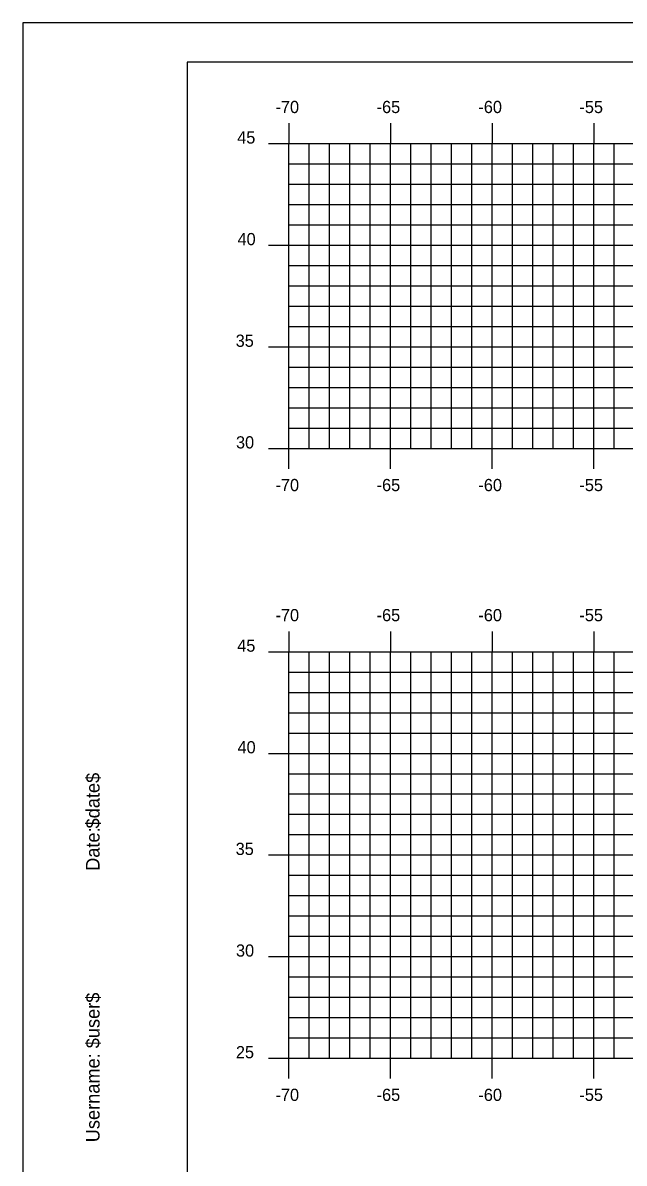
# Model space of a CAD drawing. Extents: x 1026799 to 1026969, y 394697 to 394807.
# Drawn here: x 1026799.3 to 1026828.8, y 394750.4 to 394806.5 of the extents above; entities that cross this region are included whole.
import ezdxf

# ---------------------------------------------------------------- set-up
doc = ezdxf.new("R2010")
doc.units = 0
for name, color, linetype in [('BORDER', 7, 'Continuous'), ('H_V ANNOTATION', 7, 'Continuous'), ('MAJOR', 7, 'Continuous'), ('MINOR', 7, 'Continuous'), ('PLOT BOUNDARY', 7, 'Continuous')]:
    doc.layers.add(name, color=color, linetype=linetype)

msp = doc.modelspace()

# ---------------------------------------------------------------- linework, layer by layer
at = {"layer": 'BORDER'}
for p, q in [((1026967.348, 394804.607), (1026807.348, 394804.607)), ((1026807.348, 394804.607), (1026807.348, 394699.607))]:
    msp.add_line(p, q, dxfattribs=at)
at = {"layer": 'MAJOR'}
for p, q in [((1026812.348, 394801.609), (1026812.348, 394800.607)), ((1026817.348, 394801.609), (1026817.348, 394800.607)), ((1026822.348, 394801.609), (1026822.348, 394800.607)), ((1026827.348, 394801.609), (1026827.348, 394800.607)), ((1026811.346, 394800.607), (1026812.348, 394800.607)), ((1026812.348, 394800.607), (1026952.348, 394800.607)), ((1026812.348, 394785.607), (1026812.348, 394800.607)), ((1026817.348, 394785.607), (1026817.348, 394800.607)), ((1026822.348, 394785.607), (1026822.348, 394800.607)), ((1026827.348, 394785.607), (1026827.348, 394800.607)), ((1026811.346, 394795.607), (1026812.348, 394795.607)), ((1026812.348, 394795.607), (1026952.348, 394795.607)), ((1026811.346, 394790.607), (1026812.348, 394790.607)), ((1026812.348, 394790.607), (1026952.348, 394790.607)), ((1026811.346, 394785.607), (1026812.348, 394785.607)), ((1026812.348, 394785.607), (1026952.348, 394785.607)), ((1026812.348, 394784.605), (1026812.348, 394785.607)), ((1026817.348, 394784.605), (1026817.348, 394785.607)), ((1026822.348, 394784.605), (1026822.348, 394785.607)), ((1026827.348, 394784.605), (1026827.348, 394785.607)), ((1026812.348, 394776.609), (1026812.348, 394775.607)), ((1026817.348, 394776.609), (1026817.348, 394775.607)), ((1026822.348, 394776.609), (1026822.348, 394775.607)), ((1026827.348, 394776.609), (1026827.348, 394775.607)), ((1026811.346, 394775.607), (1026812.348, 394775.607)), ((1026812.348, 394775.607), (1026952.348, 394775.607)), ((1026812.348, 394755.607), (1026812.348, 394775.607)), ((1026817.348, 394755.607), (1026817.348, 394775.607)), ((1026822.348, 394755.607), (1026822.348, 394775.607)), ((1026827.348, 394755.607), (1026827.348, 394775.607)), ((1026811.346, 394770.607), (1026812.348, 394770.607)), ((1026812.348, 394770.607), (1026952.348, 394770.607)), ((1026811.346, 394765.607), (1026812.348, 394765.607)), ((1026812.348, 394765.607), (1026952.348, 394765.607)), ((1026811.346, 394760.607), (1026812.348, 394760.607)), ((1026812.348, 394760.607), (1026952.348, 394760.607)), ((1026811.346, 394755.607), (1026812.348, 394755.607)), ((1026812.348, 394755.607), (1026952.348, 394755.607)), ((1026812.348, 394754.605), (1026812.348, 394755.607)), ((1026817.348, 394754.605), (1026817.348, 394755.607)), ((1026822.348, 394754.605), (1026822.348, 394755.607)), ((1026827.348, 394754.605), (1026827.348, 394755.607))]:
    msp.add_line(p, q, dxfattribs=at)
at = {"layer": 'MINOR'}
for p, q in [((1026813.348, 394785.607), (1026813.348, 394800.607)), ((1026814.348, 394785.607), (1026814.348, 394800.607)), ((1026815.348, 394785.607), (1026815.348, 394800.607)), ((1026816.348, 394785.607), (1026816.348, 394800.607)), ((1026818.348, 394785.607), (1026818.348, 394800.607)), ((1026819.348, 394785.607), (1026819.348, 394800.607)), ((1026820.348, 394785.607), (1026820.348, 394800.607)), ((1026821.348, 394785.607), (1026821.348, 394800.607)), ((1026823.348, 394785.607), (1026823.348, 394800.607)), ((1026824.348, 394785.607), (1026824.348, 394800.607)), ((1026825.348, 394785.607), (1026825.348, 394800.607)), ((1026826.348, 394785.607), (1026826.348, 394800.607)), ((1026828.348, 394785.607), (1026828.348, 394800.607)), ((1026812.348, 394799.607), (1026952.348, 394799.607)), ((1026812.348, 394799.607), (1026813.35, 394799.607)), ((1026812.348, 394798.607), (1026952.348, 394798.607)), ((1026812.348, 394798.607), (1026813.35, 394798.607)), ((1026812.348, 394797.607), (1026952.348, 394797.607)), ((1026812.348, 394797.607), (1026813.35, 394797.607)), ((1026812.348, 394796.607), (1026952.348, 394796.607)), ((1026812.348, 394796.607), (1026813.35, 394796.607)), ((1026812.348, 394794.607), (1026952.348, 394794.607)), ((1026812.348, 394794.607), (1026813.35, 394794.607)), ((1026812.348, 394793.607), (1026952.348, 394793.607)), ((1026812.348, 394793.607), (1026813.35, 394793.607)), ((1026812.348, 394792.607), (1026952.348, 394792.607)), ((1026812.348, 394792.607), (1026813.35, 394792.607)), ((1026812.348, 394791.607), (1026952.348, 394791.607)), ((1026812.348, 394791.607), (1026813.35, 394791.607)), ((1026812.348, 394789.607), (1026952.348, 394789.607)), ((1026812.348, 394789.607), (1026813.35, 394789.607)), ((1026812.348, 394788.607), (1026952.348, 394788.607)), ((1026812.348, 394788.607), (1026813.35, 394788.607)), ((1026812.348, 394787.607), (1026952.348, 394787.607)), ((1026812.348, 394787.607), (1026813.35, 394787.607)), ((1026812.348, 394786.607), (1026952.348, 394786.607)), ((1026812.348, 394786.607), (1026813.35, 394786.607)), ((1026813.348, 394755.607), (1026813.348, 394775.607)), ((1026814.348, 394755.607), (1026814.348, 394775.607)), ((1026815.348, 394755.607), (1026815.348, 394775.607)), ((1026816.348, 394755.607), (1026816.348, 394775.607)), ((1026818.348, 394755.607), (1026818.348, 394775.607)), ((1026819.348, 394755.607), (1026819.348, 394775.607)), ((1026820.348, 394755.607), (1026820.348, 394775.607)), ((1026821.348, 394755.607), (1026821.348, 394775.607)), ((1026823.348, 394755.607), (1026823.348, 394775.607)), ((1026824.348, 394755.607), (1026824.348, 394775.607)), ((1026825.348, 394755.607), (1026825.348, 394775.607)), ((1026826.348, 394755.607), (1026826.348, 394775.607)), ((1026828.348, 394755.607), (1026828.348, 394775.607)), ((1026812.348, 394774.607), (1026952.348, 394774.607)), ((1026812.348, 394774.607), (1026813.35, 394774.607)), ((1026812.348, 394773.607), (1026952.348, 394773.607)), ((1026812.348, 394773.607), (1026813.35, 394773.607)), ((1026812.348, 394772.607), (1026952.348, 394772.607)), ((1026812.348, 394772.607), (1026813.35, 394772.607)), ((1026812.348, 394771.607), (1026952.348, 394771.607)), ((1026812.348, 394771.607), (1026813.35, 394771.607)), ((1026812.348, 394769.607), (1026952.348, 394769.607)), ((1026812.348, 394769.607), (1026813.35, 394769.607)), ((1026812.348, 394768.607), (1026952.348, 394768.607)), ((1026812.348, 394768.607), (1026813.35, 394768.607)), ((1026812.348, 394767.607), (1026952.348, 394767.607)), ((1026812.348, 394767.607), (1026813.35, 394767.607)), ((1026812.348, 394766.607), (1026952.348, 394766.607)), ((1026812.348, 394766.607), (1026813.35, 394766.607)), ((1026812.348, 394764.607), (1026952.348, 394764.607)), ((1026812.348, 394764.607), (1026813.35, 394764.607)), ((1026812.348, 394763.607), (1026952.348, 394763.607)), ((1026812.348, 394763.607), (1026813.35, 394763.607)), ((1026812.348, 394762.607), (1026952.348, 394762.607)), ((1026812.348, 394762.607), (1026813.35, 394762.607)), ((1026812.348, 394761.607), (1026952.348, 394761.607)), ((1026812.348, 394761.607), (1026813.35, 394761.607)), ((1026812.348, 394759.607), (1026952.348, 394759.607)), ((1026812.348, 394759.607), (1026813.35, 394759.607)), ((1026812.348, 394758.607), (1026952.348, 394758.607)), ((1026812.348, 394758.607), (1026813.35, 394758.607)), ((1026812.348, 394757.607), (1026952.348, 394757.607)), ((1026812.348, 394757.607), (1026813.35, 394757.607)), ((1026812.348, 394756.607), (1026952.348, 394756.607)), ((1026812.348, 394756.607), (1026813.35, 394756.607))]:
    msp.add_line(p, q, dxfattribs=at)
at = {"layer": 'PLOT BOUNDARY'}
msp.add_lwpolyline([(1026799.254, 394696.548), (1026969.254, 394696.548), (1026969.254, 394806.548), (1026799.254, 394806.548)], close=True, dxfattribs=at)

# ---------------------------------------------------------------- texts
at = {"layer": 'BORDER'}
for s, p in [('$date$', (1026803.033, 394766.912)), ('Date:', (1026803.033, 394764.824)), ('$user$', (1026803.033, 394756.098)), ('Username:', (1026803.033, 394751.474))]:
    msp.add_text(s, height=0.6696, rotation=90, dxfattribs=at).set_placement(p)
at = {"layer": 'H_V ANNOTATION'}
for s, p in [('-70', (1026811.689, 394802.107)), ('-65', (1026816.665, 394802.107)), ('-60', (1026821.673, 394802.107)), ('-55', (1026826.644, 394802.107)), ('45', (1026809.804, 394800.607)), ('40', (1026809.82, 394795.607)), ('35', (1026809.729, 394790.607)), ('30', (1026809.745, 394785.607)), ('-70', (1026811.689, 394783.507)), ('-65', (1026816.665, 394783.507)), ('-60', (1026821.673, 394783.507)), ('-55', (1026826.644, 394783.507)), ('-70', (1026811.689, 394777.107)), ('-65', (1026816.665, 394777.107)), ('-60', (1026821.673, 394777.107)), ('-55', (1026826.644, 394777.107)), ('45', (1026809.804, 394775.607)), ('40', (1026809.82, 394770.607)), ('35', (1026809.729, 394765.607)), ('30', (1026809.745, 394760.607)), ('25', (1026809.74, 394755.607)), ('-70', (1026811.689, 394753.507)), ('-65', (1026816.665, 394753.507)), ('-60', (1026821.673, 394753.507)), ('-55', (1026826.644, 394753.507))]:
    msp.add_text(s, height=0.6, dxfattribs=at).set_placement(p)

doc.saveas('drawing.dxf')
